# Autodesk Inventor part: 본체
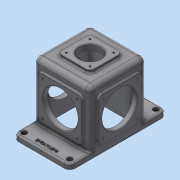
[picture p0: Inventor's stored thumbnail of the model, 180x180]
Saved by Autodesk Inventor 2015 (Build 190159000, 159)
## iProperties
Created: 2018-09
Part Number: 본체
Material: 알루미늄 6061
Document SubType Name: Modeling
Designer: mduedu
Density: 2.71 g/cm^3
Appearance: 기본값
Mass: 973.074 g
Surface Area: 1113.23 cm^2
Volume: 359.068 cm^3
Author: mduedu
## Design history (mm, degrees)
sketch "스케치1"
  geometry: L1 (90, 52.5)-(-90, 52.5); L2 (-90, 52.5)-(-90, -52.5); L3 (-90, -52.5)-(90, -52.5); L4 (90, -52.5)-(90, 52.5); L5 (90, 52.5)-(-90, -52.5); L6 (-90, 52.5)-(90, -52.5); 1 further point
  constraints: 12 end point, 2 midpoint, 2 parallel, 1 horizontal, 1 perpendicular
  dimensions: "d0" = 180 distance of L3.end L2.end; "d1" = 105 distance of L2.end L1.end
extrude "돌출1" new body sketch "스케치1" distance "d2" = 10; taper "d3" = 0 deg
sketch "스케치2"
  geometry: L1 (-52.5, -52.5)-(52.5, -52.5); L2 (52.5, -52.5)-(52.5, 52.5); L3 (52.5, 52.5)-(-52.5, 52.5); L4 (-52.5, 52.5)-(-52.5, -52.5); L5 (-52.5, -52.5)-(52.5, 52.5); L6 (52.5, -52.5)-(-52.5, 52.5); 1 further point
  constraints: 12 end point, 2 midpoint, 2 parallel, 1 horizontal, 1 perpendicular
  dimensions: "d4" = 105 distance of L3.end L2.end; "d5" = 105 distance of L2.end L1.end
extrude "돌출2" join sketch "스케치2" distance "d6" = 105; taper "d7" = 0 deg
node "작업 평면1"
sketch "스케치3"
  geometry: L1 (-52.5, 52.5)-(52.5, 52.5) reference; L2 (52.5, 52.5)-(52.5, -52.5) reference; L3 (52.5, -52.5)-(-52.5, -52.5) reference; L4 (-52.5, -52.5)-(-52.5, 52.5) reference; L5 (46.5, 46.5)-(-46.5, 46.5); L6 (-46.5, 46.5)-(-46.5, -46.5); L7 (-46.5, -46.5)-(46.5, -46.5); L8 (46.5, -46.5)-(46.5, 46.5); 1 further point
  constraints: 8 end point, 3 other
  dimensions: "d9" = 6 distance between parallel lines of L5 L1
extrude "돌출3" cut sketch "스케치3" stored distance "d10" = 105; taper "d11" = 0 deg
fillet "모깎기1" dims "d12" = 9
fillet "모깎기2" dims "d13" = 9
fillet "모깎기3" dims "d14" = 3
fillet "모깎기4" dims "d15" = 3
sketch "스케치4"
  geometry: L1 (-30, -30)-(30, -30); L2 (30, -30)-(30, 30); L3 (30, 30)-(-30, 30); L4 (-30, 30)-(-30, -30); L5 (-30, -30)-(30, 30); L6 (30, -30)-(-30, 30); 1 further point
  constraints: 12 end point, 2 midpoint, 2 parallel, 1 horizontal, 1 perpendicular
  dimensions: "d16" = 60 distance of L3.end L2.end; "d17" = 60 distance of L2.end L1.end
extrude "돌출4" join sketch "스케치4" distance "d18" = 5; taper "d19" = 0 deg
fillet "모깎기5" dims "d20" = 8
fillet "모깎기6" dims "d21" = 3
sketch "스케치5"
  geometry: C1 r 20 at (0, 0); 1 further point
  constraints: 1 centre point, 1 coincident
  dimensions: "d22" = 40 diameter of C1
extrude "돌출5" cut sketch "스케치5" stored distance "d23" = 5; taper "d24" = 0 deg
sketch "스케치6"
  geometry: L1 (50, 17.5)-(130, 17.5); L2 (130, 17.5)-(130, 97.5); L3 (130, 97.5)-(50, 97.5); L4 (50, 97.5)-(50, 17.5); L5 (50, 17.5)-(130, 97.5); L6 (130, 17.5)-(50, 97.5); L7 (0, 0)-(180, 0) reference; 4 further points
  constraints: 12 end point, 4 midpoint, 2 parallel, 1 horizontal, 1 perpendicular, 1 vertical alignment
  dimensions: "d25" = 80 distance of L3.end L2.end; "d26" = 80 distance of L2.end L1.end; "d27" = 57.5 distance of point (90, 0) point (90, 57.5)
extrude "돌출6" join sketch "스케치6" distance "d28" = 3; taper "d29" = 0 deg
fillet "모깎기7" dims "d30" = 8
sketch "스케치7"
  geometry: C1 r 32.5 at (90, 57.5); 1 further point
  constraints: 1 centre point, 1 vertical alignment
  dimensions: "d32" = 65 diameter of C1; "d33" = 57.5 distance of C1.centre point (90, 0)
extrude "돌출7" cut sketch "스케치7" stored distance "d34" = 3; taper "d35" = 0 deg
fillet "모깎기9" dims "d36" = 3
sketch "스케치8"
  geometry: L1 (3.5, 7.5)-(83.5, 7.5); L2 (83.5, 7.5)-(83.5, 87.5); L3 (83.5, 87.5)-(3.5, 87.5); L4 (3.5, 87.5)-(3.5, 7.5); L5 (3.5, 7.5)-(83.5, 87.5); L6 (83.5, 7.5)-(3.5, 87.5); L7 (-9, -10)-(96, -10) reference; C1 r 32.5 at (43.5, 47.5); 4 further points
  constraints: 12 end point, 4 midpoint, 2 parallel, 1 centre point, 1 coincident, 1 horizontal, 1 perpendicular, 1 vertical alignment
  dimensions: "d37" = 80 distance of L3.end L2.end; "d38" = 80 distance of L2.end L1.end; "d39" = 57.5 distance from line of point (43.5, 47.5) L7; "d40" = 65 diameter of C1
extrude "돌출8" join sketch "스케치8" distance "d41" = 3; taper "d42" = 0 deg
fillet "모깎기10" dims "d43" = 8
extrude "돌출9" cut sketch "스케치8" stored distance "d44" = 3; taper "d45" = 0 deg
fillet "모깎기11" dims "d46" = 3
sketch "스케치9"
  geometry: L1 (50, 89.5)-(50, 25.5) reference; L2 (58, 17.5)-(122, 17.5) reference; L3 (130, 25.5)-(130, 89.5) reference; L4 (122, 97.5)-(58, 97.5) reference; C1 r 32.5 at (90, 57.5) reference; A1 r 8 centre (58, 89.5) between (58, 97.5) and (50, 89.5) reference; A2 r 8 centre (58, 25.5) between (50, 25.5) and (58, 17.5) reference; A3 r 8 centre (122, 25.5) between (122, 17.5) and (130, 25.5) reference; A4 r 8 centre (122, 89.5) between (130, 89.5) and (122, 97.5) reference; 5 further points
  constraints: 4 coincident
hole "구멍1" sketch "스케치9" at (58, 89.5), (122, 89.5), (122, 25.5), (58, 25.5) diameter "d47" = 3.242; stored, may be unused: countersink angle "d51" = 90 deg, drill point angle "d53" = 118 deg; dims "d48" = 6, "d49" = 4, "d50" = 2, "d52" = 9
sketch "스케치10"
  geometry: L1 (11.5, 7.5)-(75.5, 7.5) reference; L2 (83.5, 15.5)-(83.5, 79.5) reference; L3 (75.5, 87.5)-(11.5, 87.5) reference; L4 (3.5, 79.5)-(3.5, 15.5) reference; C1 r 32.5 at (43.5, 47.5) reference; A1 r 8 centre (11.5, 15.5) between (3.5, 15.5) and (11.5, 7.5) reference; A2 r 8 centre (75.5, 15.5) between (75.5, 7.5) and (83.5, 15.5) reference; A3 r 8 centre (75.5, 79.5) between (83.5, 79.5) and (75.5, 87.5) reference; A4 r 8 centre (11.5, 79.5) between (11.5, 87.5) and (3.5, 79.5) reference; 5 further points
  constraints: 4 coincident
hole "구멍2" sketch "스케치10" at (11.5, 79.5), (75.5, 79.5), (75.5, 15.5), (11.5, 15.5) diameter "d54" = 3.242; stored, may be unused: countersink angle "d58" = 90 deg, drill point angle "d60" = 118 deg; dims "d55" = 6, "d56" = 4, "d57" = 2, "d59" = 9
sketch "스케치11"
  geometry: L1 (22, 30)-(-22, 30) reference; L2 (-30, 22)-(-30, -22) reference; L3 (-22, -30)-(22, -30) reference; L4 (30, -22)-(30, 22) reference; C1 r 20 at (0, 0) reference; A1 r 8 centre (22, 22) between (30, 22) and (22, 30) reference; A2 r 8 centre (-22, 22) between (-22, 30) and (-30, 22) reference; A3 r 8 centre (-22, -22) between (-30, -22) and (-22, -30) reference; A4 r 8 centre (22, -22) between (22, -30) and (30, -22) reference; 5 further points
  constraints: 4 coincident
hole "구멍3" sketch "스케치11" at (-22, 22), (22, 22), (22, -22), (-22, -22) diameter "d61" = 3.242; stored, may be unused: countersink angle "d65" = 90 deg, drill point angle "d67" = 118 deg; dims "d62" = 7, "d63" = 4, "d64" = 2, "d66" = 9
fillet "모깎기12" dims "d68" = 10
sketch "스케치12"
  geometry: L1 (-90, 42.5)-(-90, -42.5) reference; L2 (-80, -52.5)-(-43.5, -52.5) reference; L3 (-52.5, -43.5)-(-52.5, 43.5) reference; L4 (-43.5, 52.5)-(-80, 52.5) reference; A1 r 10 centre (-80, 42.5) between (-80, 52.5) and (-90, 42.5) reference; A2 r 10 centre (-80, -42.5) between (-90, -42.5) and (-80, -52.5) reference; A3 r 9 centre (-43.5, -43.5) between (-52.5, -43.5) and (-43.5, -52.5) reference; A4 r 9 centre (-43.5, 43.5) between (-43.5, 52.5) and (-52.5, 43.5) reference; 3 further points
  constraints: 2 coincident
hole "구멍4" sketch "스케치12" at (-80, 42.5), (-80, -42.5) diameter "d70" = 10; stored, may be unused: countersink angle "d74" = 90 deg, drill point angle "d76" = 118 deg; dims "d71" = 6, "d72" = 4, "d73" = 2, "d75" = 9
fillet "모깎기13" dims "d77" = 3
fillet "모깎기14" dims "d78" = 3
chamfer "모따기1" distance "d79" = 1; stored, may be unused: second distance "d80" = 2, angle "d81" = 45 deg
sketch "스케치13"
  geometry: L1 (90, -42.5)-(90, 42.5) reference; 2 further points
  constraints: 1 horizontal alignment, 1 other
  dimensions: "d82" = 10 distance from line of point (80, 0) L1
feature "엠보싱1" sketch "스케치13" dims "d83" = 0.5, "d84" = 0
node "솔리드1"
mirror "대칭1"
mirror "대칭2"
mirror "대칭3"
node "투영된 루프1"
node "투영된 루프2"
node "투영된 루프3"
node "투영된 루프4"
node "투영된 루프5"
other parameters: "d8" = -6
